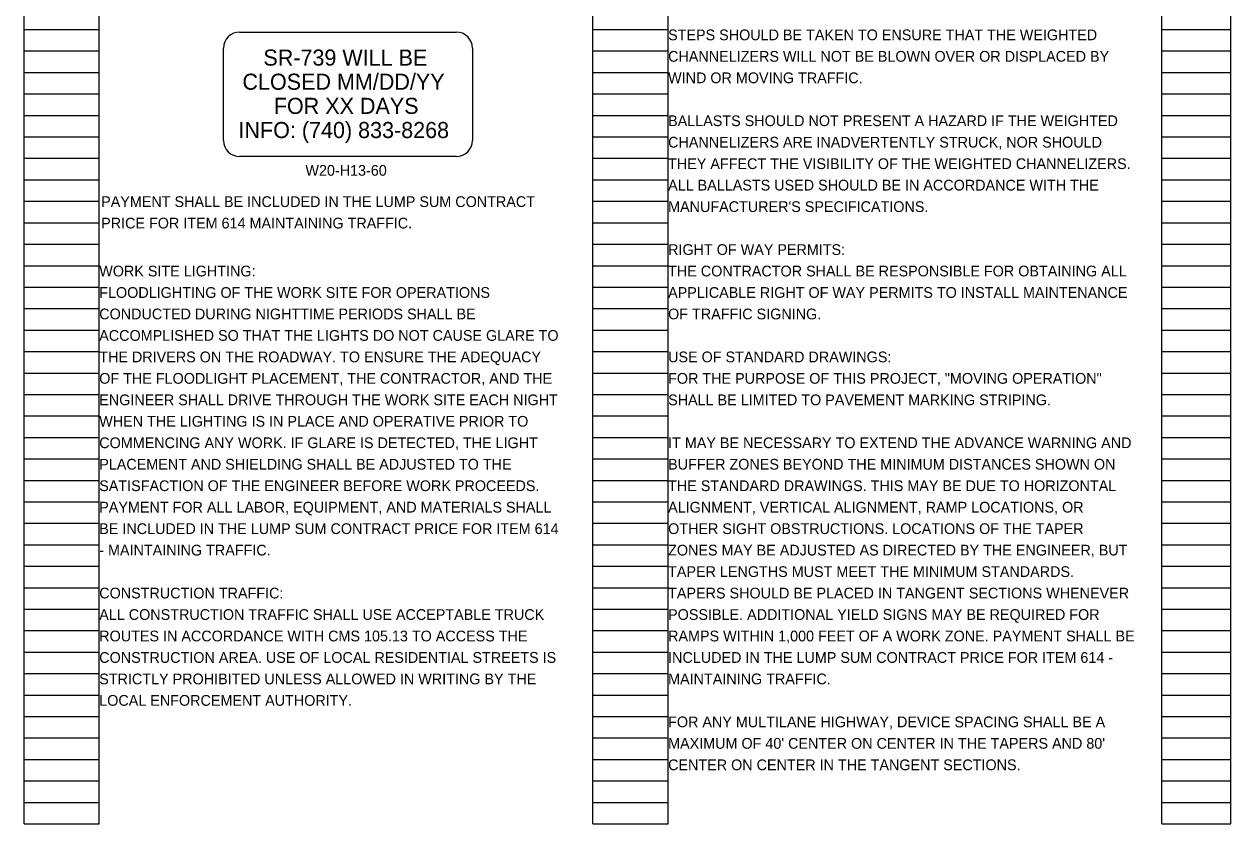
# Model space of a CAD drawing. Extents: x 63 to 145.9, y -75 to 21.1.
# Drawn here: x 79.23 to 94.97, y 0.98 to 11.41 of the extents above; entities that cross this region are included whole.
import ezdxf

# ---------------------------------------------------------------- set-up
doc = ezdxf.new("R2010")
doc.units = 0
for name, color, linetype in [('AP_P_Airside', 7, 'Continuous'), ('Default', 7, 'Continuous'), ('SC_Scratch1', 7, 'Continuous')]:
    doc.layers.add(name, color=color, linetype=linetype)

msp = doc.modelspace()

# ---------------------------------------------------------------- linework, layer by layer
at = {"layer": 'SC_Scratch1'}
for p, q in [((79.226, 0.98), (79.226, 21.14)), ((80.206, 0.98), (80.206, 21.14)), ((86.646, 0.98), (86.646, 21.14)), ((87.626, 0.98), (87.626, 21.14)), ((94.066, 0.98), (94.066, 21.14)), ((94.966, 0.98), (94.966, 21.14)), ((79.226, 11.34), (80.206, 11.34)), ((86.646, 11.34), (87.626, 11.34)), ((94.066, 11.34), (94.966, 11.34)), ((82.037, 11.307), (84.864, 11.307)), ((79.226, 11.06), (80.206, 11.06)), ((81.828, 9.892), (81.828, 11.098)), ((85.074, 11.098), (85.074, 9.892)), ((86.646, 11.06), (87.626, 11.06)), ((94.066, 11.06), (94.966, 11.06)), ((79.226, 10.78), (80.206, 10.78)), ((86.646, 10.78), (87.626, 10.78)), ((94.066, 10.78), (94.966, 10.78)), ((79.226, 10.5), (80.206, 10.5)), ((86.646, 10.5), (87.626, 10.5)), ((94.066, 10.5), (94.966, 10.5)), ((79.226, 10.22), (80.206, 10.22)), ((86.646, 10.22), (87.626, 10.22)), ((94.066, 10.22), (94.966, 10.22)), ((79.226, 9.94), (80.206, 9.94)), ((86.646, 9.94), (87.626, 9.94)), ((94.066, 9.94), (94.966, 9.94)), ((79.226, 9.66), (80.206, 9.66)), ((84.864, 9.683), (82.037, 9.683)), ((86.646, 9.66), (87.626, 9.66)), ((94.066, 9.66), (94.966, 9.66)), ((79.226, 9.38), (80.206, 9.38)), ((86.646, 9.38), (87.626, 9.38)), ((94.066, 9.38), (94.966, 9.38)), ((79.226, 9.1), (80.206, 9.1)), ((86.646, 9.1), (87.626, 9.1)), ((94.066, 9.1), (94.966, 9.1)), ((79.226, 8.82), (80.206, 8.82)), ((86.646, 8.82), (87.626, 8.82)), ((94.066, 8.82), (94.966, 8.82)), ((79.226, 8.54), (80.206, 8.54)), ((86.646, 8.54), (87.626, 8.54)), ((94.066, 8.54), (94.966, 8.54)), ((79.226, 8.26), (80.206, 8.26)), ((86.646, 8.26), (87.626, 8.26)), ((94.066, 8.26), (94.966, 8.26)), ((79.226, 7.98), (80.206, 7.98)), ((86.646, 7.98), (87.626, 7.98)), ((94.066, 7.98), (94.966, 7.98)), ((79.226, 7.7), (80.206, 7.7)), ((86.646, 7.7), (87.626, 7.7)), ((94.066, 7.7), (94.966, 7.7)), ((79.226, 7.42), (80.206, 7.42)), ((86.646, 7.42), (87.626, 7.42)), ((94.066, 7.42), (94.966, 7.42)), ((79.226, 7.14), (80.206, 7.14)), ((86.646, 7.14), (87.626, 7.14)), ((94.066, 7.14), (94.966, 7.14)), ((79.226, 6.86), (80.206, 6.86)), ((86.646, 6.86), (87.626, 6.86)), ((94.066, 6.86), (94.966, 6.86)), ((79.226, 6.58), (80.206, 6.58)), ((86.646, 6.58), (87.626, 6.58)), ((94.066, 6.58), (94.966, 6.58)), ((79.226, 6.3), (80.206, 6.3)), ((86.646, 6.3), (87.626, 6.3)), ((94.066, 6.3), (94.966, 6.3)), ((79.226, 6.02), (80.206, 6.02)), ((86.646, 6.02), (87.626, 6.02)), ((94.066, 6.02), (94.966, 6.02)), ((79.226, 5.74), (80.206, 5.74)), ((86.646, 5.74), (87.626, 5.74)), ((94.066, 5.74), (94.966, 5.74)), ((79.226, 5.46), (80.206, 5.46)), ((86.646, 5.46), (87.626, 5.46)), ((94.066, 5.46), (94.966, 5.46)), ((79.226, 5.18), (80.206, 5.18)), ((86.646, 5.18), (87.626, 5.18)), ((94.066, 5.18), (94.966, 5.18)), ((79.226, 4.9), (80.206, 4.9)), ((86.646, 4.9), (87.626, 4.9)), ((94.066, 4.9), (94.966, 4.9)), ((79.226, 4.62), (80.206, 4.62)), ((86.646, 4.62), (87.626, 4.62)), ((94.066, 4.62), (94.966, 4.62)), ((79.226, 4.34), (80.206, 4.34)), ((86.646, 4.34), (87.626, 4.34)), ((94.066, 4.34), (94.966, 4.34)), ((79.226, 4.06), (80.206, 4.06)), ((86.646, 4.06), (87.626, 4.06)), ((94.066, 4.06), (94.966, 4.06)), ((79.226, 3.78), (80.206, 3.78)), ((86.646, 3.78), (87.626, 3.78)), ((94.066, 3.78), (94.966, 3.78)), ((79.226, 3.5), (80.206, 3.5)), ((86.646, 3.5), (87.626, 3.5)), ((94.066, 3.5), (94.966, 3.5)), ((79.226, 3.22), (80.206, 3.22)), ((86.646, 3.22), (87.626, 3.22)), ((94.066, 3.22), (94.966, 3.22)), ((79.226, 2.94), (80.206, 2.94)), ((86.646, 2.94), (87.626, 2.94)), ((94.066, 2.94), (94.966, 2.94)), ((79.226, 2.66), (80.206, 2.66)), ((86.646, 2.66), (87.626, 2.66)), ((94.066, 2.66), (94.966, 2.66)), ((79.226, 2.38), (80.206, 2.38)), ((86.646, 2.38), (87.626, 2.38)), ((94.066, 2.38), (94.966, 2.38)), ((79.226, 2.1), (80.206, 2.1)), ((86.646, 2.1), (87.626, 2.1)), ((94.066, 2.1), (94.966, 2.1)), ((79.226, 1.82), (80.206, 1.82)), ((86.646, 1.82), (87.626, 1.82)), ((94.066, 1.82), (94.966, 1.82)), ((79.226, 1.54), (80.206, 1.54)), ((86.646, 1.54), (87.626, 1.54)), ((94.066, 1.54), (94.966, 1.54)), ((79.226, 1.26), (80.206, 1.26)), ((86.646, 1.26), (87.626, 1.26)), ((94.066, 1.26), (94.966, 1.26)), ((79.226, 0.98), (80.206, 0.98)), ((86.646, 0.98), (87.626, 0.98)), ((94.066, 0.98), (94.966, 0.98))]:
    msp.add_line(p, q, dxfattribs=at)
for centre, start, end in [((82.037, 11.098), 90, 180), ((84.864, 11.098), 0, 90), ((82.037, 9.892), 180, 270), ((84.864, 9.892), 270, 0)]:
    msp.add_arc(centre, 0.209, start, end, dxfattribs=at)

# ---------------------------------------------------------------- texts
at = {"layer": 'AP_P_Airside'}
for s, p in [('STEPS SHOULD BE TAKEN TO ENSURE THAT THE WEIGHTED ', (87.626, 11.2)), ('CHANNELIZERS WILL NOT BE BLOWN OVER OR DISPLACED BY ', (87.626, 10.92)), ('WIND OR MOVING TRAFFIC.', (87.626, 10.64)), ('BALLASTS SHOULD NOT PRESENT A HAZARD IF THE WEIGHTED ', (87.626, 10.08)), ('CHANNELIZERS ARE INADVERTENTLY STRUCK, NOR SHOULD ', (87.626, 9.8)), ('THEY AFFECT THE VISIBILITY OF THE WEIGHTED CHANNELIZERS. ', (87.626, 9.52)), ('ALL BALLASTS USED SHOULD BE IN ACCORDANCE WITH THE ', (87.626, 9.24)), ("MANUFACTURER'S SPECIFICATIONS.", (87.626, 8.96)), ('RIGHT OF WAY PERMITS:', (87.626, 8.4)), ('WORK SITE LIGHTING:', (80.206, 8.12)), ('THE CONTRACTOR SHALL BE RESPONSIBLE FOR OBTAINING ALL ', (87.626, 8.12)), ('FLOODLIGHTING OF THE WORK SITE FOR OPERATIONS ', (80.206, 7.84)), ('APPLICABLE RIGHT OF WAY PERMITS TO INSTALL MAINTENANCE ', (87.626, 7.84)), ('CONDUCTED DURING NIGHTTIME PERIODS SHALL BE ', (80.206, 7.56)), ('OF TRAFFIC SIGNING.', (87.626, 7.56)), ('ACCOMPLISHED SO THAT THE LIGHTS DO NOT CAUSE GLARE TO ', (80.206, 7.28)), ('THE DRIVERS ON THE ROADWAY. TO ENSURE THE ADEQUACY ', (80.206, 7)), ('USE OF STANDARD DRAWINGS:', (87.626, 7)), ('OF THE FLOODLIGHT PLACEMENT, THE CONTRACTOR, AND THE ', (80.206, 6.72)), ('FOR THE PURPOSE OF THIS PROJECT, "MOVING OPERATION" ', (87.626, 6.72)), ('ENGINEER SHALL DRIVE THROUGH THE WORK SITE EACH NIGHT ', (80.206, 6.44)), ('SHALL BE LIMITED TO PAVEMENT MARKING STRIPING.', (87.626, 6.44)), ('WHEN THE LIGHTING IS IN PLACE AND OPERATIVE PRIOR TO ', (80.206, 6.16)), ('COMMENCING ANY WORK. IF GLARE IS DETECTED, THE LIGHT ', (80.206, 5.88)), ('IT MAY BE NECESSARY TO EXTEND THE ADVANCE WARNING AND ', (87.626, 5.88)), ('PLACEMENT AND SHIELDING SHALL BE ADJUSTED TO THE ', (80.206, 5.6)), ('BUFFER ZONES BEYOND THE MINIMUM DISTANCES SHOWN ON ', (87.626, 5.6)), ('SATISFACTION OF THE ENGINEER BEFORE WORK PROCEEDS. ', (80.206, 5.32)), ('THE STANDARD DRAWINGS. THIS MAY BE DUE TO HORIZONTAL ', (87.626, 5.32)), ('PAYMENT FOR ALL LABOR, EQUIPMENT, AND MATERIALS SHALL ', (80.206, 5.04)), ('ALIGNMENT, VERTICAL ALIGNMENT, RAMP LOCATIONS, OR ', (87.626, 5.04)), ('BE INCLUDED IN THE LUMP SUM CONTRACT PRICE FOR ITEM 614 ', (80.206, 4.76)), ('OTHER SIGHT OBSTRUCTIONS. LOCATIONS OF THE TAPER ', (87.626, 4.76)), ('- MAINTAINING TRAFFIC.', (80.206, 4.48)), ('ZONES MAY BE ADJUSTED AS DIRECTED BY THE ENGINEER, BUT ', (87.626, 4.48)), ('TAPER LENGTHS MUST MEET THE MINIMUM STANDARDS. ', (87.626, 4.2)), ('CONSTRUCTION TRAFFIC:', (80.206, 3.92)), ('TAPERS SHOULD BE PLACED IN TANGENT SECTIONS WHENEVER ', (87.626, 3.92)), ('ALL CONSTRUCTION TRAFFIC SHALL USE ACCEPTABLE TRUCK ', (80.206, 3.64)), ('POSSIBLE. ADDITIONAL YIELD SIGNS MAY BE REQUIRED FOR ', (87.626, 3.64)), ('ROUTES IN ACCORDANCE WITH CMS 105.13 TO ACCESS THE ', (80.206, 3.36)), ('RAMPS WITHIN 1,000 FEET OF A WORK ZONE. PAYMENT SHALL BE ', (87.626, 3.36)), ('CONSTRUCTION AREA. USE OF LOCAL RESIDENTIAL STREETS IS ', (80.206, 3.08)), ('INCLUDED IN THE LUMP SUM CONTRACT PRICE FOR ITEM 614 - ', (87.626, 3.08)), ('STRICTLY PROHIBITED UNLESS ALLOWED IN WRITING BY THE ', (80.206, 2.8)), ('MAINTAINING TRAFFIC.', (87.626, 2.8)), ('LOCAL ENFORCEMENT AUTHORITY.', (80.206, 2.52)), ('FOR ANY MULTILANE HIGHWAY, DEVICE SPACING SHALL BE A ', (87.626, 2.24)), ("MAXIMUM OF 40' CENTER ON CENTER IN THE TAPERS AND 80' ", (87.626, 1.96)), ('CENTER ON CENTER IN THE TANGENT SECTIONS.', (87.626, 1.68))]:
    msp.add_text(s, height=0.14, dxfattribs=at).set_placement(p)
at = {"layer": 'Default'}
for s, p in [('W20-H13-60', (82.895, 9.433)), ('PAYMENT SHALL BE INCLUDED IN THE LUMP SUM CONTRACT ', (80.231, 9.025)), ('PRICE FOR ITEM 614 MAINTAINING TRAFFIC.', (80.231, 8.745))]:
    msp.add_text(s, height=0.14, dxfattribs=at).set_placement(p)
at = {"layer": 'SC_Scratch1'}
for s, p in [('SR-739 WILL BE', (82.347, 10.869)), ('CLOSED MM/DD/YY', (82.074, 10.554)), ('FOR XX DAYS', (82.483, 10.239)), ('INFO: (740) 833-8268', (82.022, 9.924))]:
    msp.add_text(s, height=0.21, dxfattribs=at).set_placement(p)

doc.saveas('drawing.dxf')
